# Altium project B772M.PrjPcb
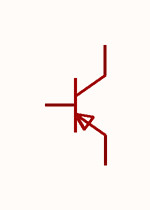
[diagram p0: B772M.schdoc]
1 sheet, 1 parts. Net scope: global (net labels, ports and power ports of the same name join across sheets).

## Sheet B772M.schdoc
size 127 x 101 mm

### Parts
Q?  b772m(range:200-400)  [TO-252-3_L6.5-W5.8-P4.58-BL]  (value not drawn)

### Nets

Not connected (* = marked no-connect by the designer): Q? 1(B) 2(C) 3(E)

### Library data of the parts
Q? = b772m(range:200-400): 晶体管类型:PNP;集电极电流(Ic):3A;集射极击穿电压(Vceo):30V;耗散功率(Pd):1.25W;直流电流增益(hFE):60;; Manufacturer: CJ(江苏长电/长晶); AddInBom: yes; ModelId: b30bfce30d0f4a429b5e4d5ada8cad65; ModelTransform: 249.9995,380.57715,0,0,0,0,0,38.779,0; type: PNP; Current - Collector(Ic): 3A; Collector - Emitter Voltage VCEO: 30V; Pd - Power Dissipation: 1.25W; DC Current Gain: 60; Transition frequency(fT): 80MHz; Current - Collector Cutoff: 1uA; Vce Saturation(VCE(sat)): 500mV; Emitter-Base Voltage(Vebo): 6V; Number: 1个PNP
